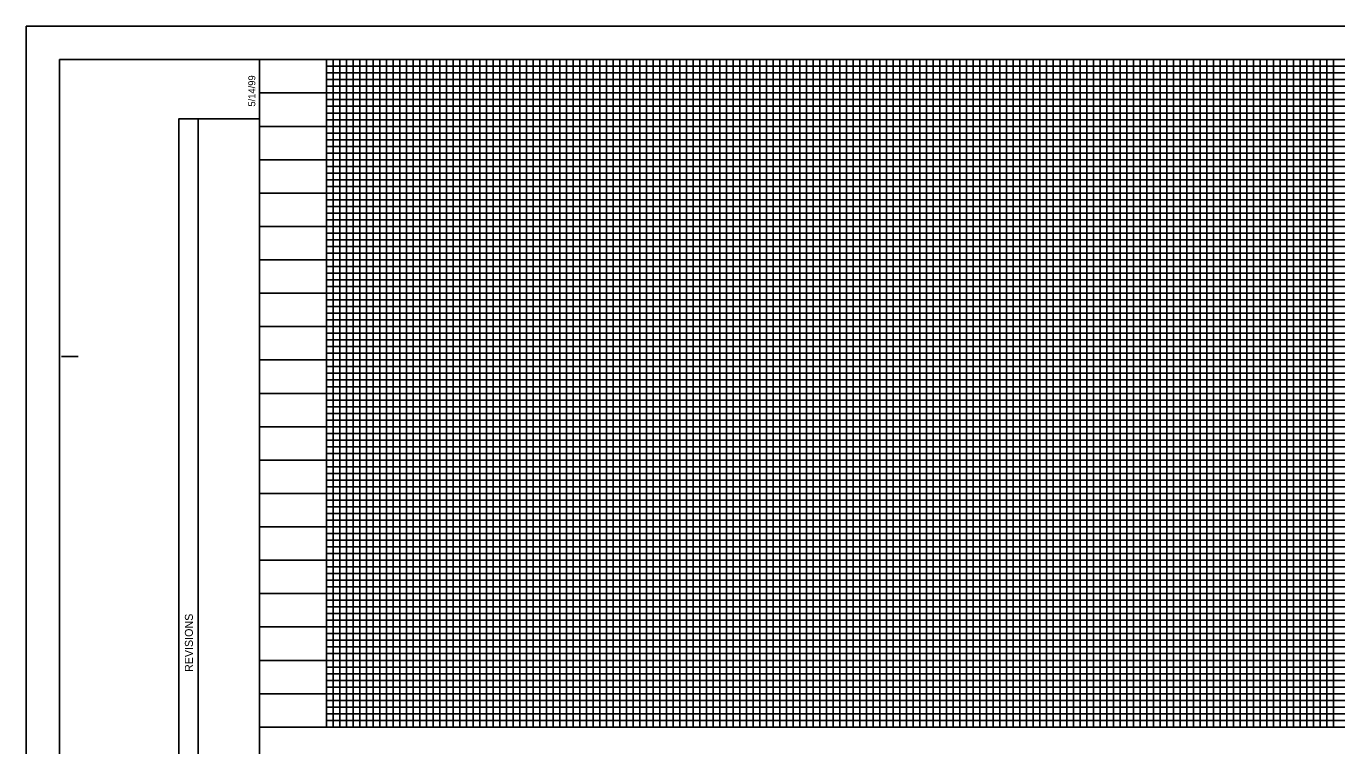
# Model space of a CAD drawing. Extents: x 1852853 to 1854818, y 258638 to 259738.
# Drawn here: x 1852853 to 1853836, y 259199 to 259738 of the extents above; entities that cross this region are included whole.
import ezdxf

# ---------------------------------------------------------------- set-up
doc = ezdxf.new("R2010")
doc.units = 0
for name, color, linetype in [('Old_Level_41', 7, 'Continuous'), ('Old_Level_43', 7, 'Continuous'), ('Old_Level_46', 7, 'Continuous'), ('Old_Level_62', 7, 'Continuous'), ('Old_Level_63', 7, 'Continuous'), ('Scratch_Level_3', 7, 'Continuous'), ('Sheet Block Revision CELL', 7, 'Continuous'), ('Sheet Profile CELL', 7, 'Continuous'), ('Sheet Profile Grid Major CELL', 7, 'Continuous'), ('Sheet Profile Grid Middle CELL', 7, 'Continuous'), ('Sheet Profile Grid Minor CELL', 7, 'Continuous')]:
    doc.layers.add(name, color=color, linetype=linetype)

msp = doc.modelspace()

# ---------------------------------------------------------------- linework, layer by layer
at = {"layer": 'Old_Level_41'}
msp.add_line((1852879.58, 259490.99), (1852892.08, 259490.99), dxfattribs=at)
at = {"layer": 'Old_Level_43'}
msp.add_line((1853078.08, 259703.49), (1853078.08, 259703.49), dxfattribs=at)
at = {"layer": 'Old_Level_46'}
msp.add_line((1853028.08, 259713.49), (1853028.08, 259713.49), dxfattribs=at)
at = {"layer": 'Old_Level_62'}
msp.add_lwpolyline([(1852878.08, 258663.49), (1854528.08, 258663.49), (1854528.08, 259713.49), (1852878.08, 259713.49)], close=True, dxfattribs=at)
at = {"layer": 'Old_Level_63'}
msp.add_lwpolyline([(1852853.08, 258638.49), (1854553.08, 258638.49), (1854553.08, 259738.49), (1852853.08, 259738.49)], close=True, dxfattribs=at)
at = {"layer": 'Scratch_Level_3'}
msp.add_lwpolyline([(1853078.08, 259713.49), (1853078.08, 259213.49), (1854478.08, 259213.49), (1854478.08, 259481.84), (1854328.03, 259481.84), (1854328.03, 259713.49)], close=True, dxfattribs=at)
at = {"layer": 'Sheet Block Revision CELL'}
msp.add_line((1852982.09, 258878.59), (1852982.08, 259669.23), dxfattribs=at)
msp.add_lwpolyline([(1852967.54, 258878.57), (1852967.54, 259669.22), (1853028.08, 259669.24), (1853028.08, 258878.59)], close=True, dxfattribs=at)
at = {"layer": 'Sheet Profile CELL'}
msp.add_line((1853028.08, 259213.49), (1854528.08, 259213.49), dxfattribs=at)
msp.add_lwpolyline([(1854528.08, 259713.49), (1853028.08, 259713.49), (1853028.08, 258663.49), (1854528.08, 258663.49)], close=True, dxfattribs=at)
at = {"layer": 'Sheet Profile Grid Major CELL'}
for points in [[(1854328.08, 259663.49), (1853028.08, 259663.49), (1853028.08, 259713.49), (1854328.08, 259713.49)], [(1853078.08, 259713.49), (1853078.08, 259213.49), (1853128.08, 259213.49), (1853128.08, 259713.49)], [(1853178.08, 259713.49), (1853178.08, 259213.49), (1853228.08, 259213.49), (1853228.08, 259713.49)], [(1853278.08, 259713.49), (1853278.08, 259213.49), (1853328.08, 259213.49), (1853328.08, 259713.49)], [(1853378.08, 259713.49), (1853378.08, 259213.49), (1853428.08, 259213.49), (1853428.08, 259713.49)], [(1853478.08, 259713.49), (1853478.08, 259213.49), (1853528.08, 259213.49), (1853528.08, 259713.49)], [(1853578.08, 259713.49), (1853578.08, 259213.49), (1853628.08, 259213.49), (1853628.08, 259713.49)], [(1853678.08, 259713.49), (1853678.08, 259213.49), (1853728.08, 259213.49), (1853728.08, 259713.49)], [(1853778.08, 259713.49), (1853778.08, 259213.49), (1853828.08, 259213.49), (1853828.08, 259713.49)], [(1854328.08, 259563.49), (1853028.08, 259563.49), (1853028.08, 259613.49), (1854328.08, 259613.49)], [(1854528.08, 259463.49), (1853028.08, 259463.49), (1853028.08, 259513.49), (1854328.03, 259513.49)], [(1854528.08, 259363.49), (1853028.08, 259363.49), (1853028.08, 259413.49), (1854528.08, 259413.49)], [(1854528.08, 259263.49), (1853028.08, 259263.49), (1853028.08, 259313.49), (1854528.08, 259313.49)]]:
    msp.add_lwpolyline(points, dxfattribs=at)
at = {"layer": 'Sheet Profile Grid Middle CELL'}
for points in [[(1853028.08, 259713.49), (1853028.08, 259688.49), (1854328.08, 259688.49)], [(1853103.08, 259213.49), (1853103.08, 259713.49)], [(1853153.08, 259713.49), (1853153.08, 259213.49), (1853203.08, 259213.49), (1853203.08, 259713.49)], [(1853253.08, 259713.49), (1853253.08, 259213.49), (1853303.08, 259213.49), (1853303.08, 259713.49)], [(1853353.08, 259713.49), (1853353.08, 259213.49), (1853403.08, 259213.49), (1853403.08, 259713.49)], [(1853453.08, 259713.49), (1853453.08, 259213.49), (1853503.08, 259213.49), (1853503.08, 259713.49)], [(1853553.08, 259713.49), (1853553.08, 259213.49), (1853603.08, 259213.49), (1853603.08, 259713.49)], [(1853653.08, 259713.49), (1853653.08, 259213.49), (1853703.08, 259213.49), (1853703.08, 259713.49)], [(1853753.08, 259713.49), (1853753.08, 259213.49), (1853803.08, 259213.49), (1853803.08, 259713.49)], [(1854328.08, 259638.49), (1853028.08, 259638.49), (1853028.08, 259588.49), (1854328.08, 259588.49)], [(1854328.08, 259538.49), (1853028.08, 259538.49), (1853028.08, 259488.49), (1854328.03, 259488.49)], [(1854528.08, 259438.49), (1853028.08, 259438.49), (1853028.08, 259388.49), (1854528.08, 259388.49)], [(1854528.08, 259338.49), (1853028.08, 259338.49), (1853028.08, 259288.49), (1854528.08, 259288.49)], [(1854528.08, 259238.49), (1853028.08, 259238.49)]]:
    msp.add_lwpolyline(points, dxfattribs=at)
at = {"layer": 'Sheet Profile Grid Minor CELL'}
for points in [[(1853078.08, 259708.49), (1854328.08, 259708.49)], [(1853083.08, 259713.49), (1853083.08, 259213.49), (1853088.08, 259213.49), (1853088.08, 259713.49)], [(1853093.08, 259713.49), (1853093.08, 259213.49), (1853098.08, 259213.49), (1853098.08, 259713.49)], [(1853108.08, 259713.49), (1853108.08, 259213.49), (1853113.08, 259213.49), (1853113.08, 259713.49)], [(1853118.08, 259713.49), (1853118.08, 259213.49), (1853123.08, 259213.49), (1853123.08, 259713.49)], [(1853133.08, 259713.49), (1853133.08, 259213.49), (1853138.08, 259213.49), (1853138.08, 259713.49)], [(1853143.08, 259713.49), (1853143.08, 259213.49), (1853148.08, 259213.49), (1853148.08, 259713.49)], [(1853158.08, 259713.49), (1853158.08, 259213.49), (1853163.08, 259213.49), (1853163.08, 259713.49)], [(1853168.08, 259713.49), (1853168.08, 259213.49), (1853173.08, 259213.49), (1853173.08, 259713.49)], [(1853183.08, 259713.49), (1853183.08, 259213.49), (1853188.08, 259213.49), (1853188.08, 259713.49)], [(1853193.08, 259713.49), (1853193.08, 259213.49), (1853198.08, 259213.49), (1853198.08, 259713.49)], [(1853208.08, 259713.49), (1853208.08, 259213.49), (1853213.08, 259213.49), (1853213.08, 259713.49)], [(1853218.08, 259713.49), (1853218.08, 259213.49), (1853223.08, 259213.49), (1853223.08, 259713.49)], [(1853233.08, 259713.49), (1853233.08, 259213.49), (1853238.08, 259213.49), (1853238.08, 259713.49)], [(1853243.08, 259213.49), (1853248.08, 259213.49), (1853248.08, 259713.49)], [(1853243.08, 259713.49), (1853243.08, 259213.49)], [(1853258.08, 259713.49), (1853258.08, 259213.49), (1853263.08, 259213.49), (1853263.08, 259713.49)], [(1853268.08, 259713.49), (1853268.08, 259213.49), (1853273.08, 259213.49), (1853273.08, 259713.49)], [(1853283.08, 259713.49), (1853283.08, 259213.49), (1853288.08, 259213.49), (1853288.08, 259713.49)], [(1853293.08, 259713.49), (1853293.08, 259213.49), (1853298.08, 259213.49), (1853298.08, 259713.49)], [(1853308.08, 259713.49), (1853308.08, 259213.49), (1853313.08, 259213.49), (1853313.08, 259713.49)], [(1853318.08, 259713.49), (1853318.08, 259213.49), (1853323.08, 259213.49), (1853323.08, 259713.49)], [(1853333.08, 259713.49), (1853333.08, 259213.49), (1853338.08, 259213.49), (1853338.08, 259713.49)], [(1853343.08, 259713.49), (1853343.08, 259213.49), (1853348.08, 259213.49), (1853348.08, 259713.49)], [(1853358.08, 259713.49), (1853358.08, 259213.49), (1853363.08, 259213.49), (1853363.08, 259713.49)], [(1853368.08, 259713.49), (1853368.08, 259213.49), (1853373.08, 259213.49), (1853373.08, 259713.49)], [(1853383.08, 259713.49), (1853383.08, 259213.49), (1853388.08, 259213.49), (1853388.08, 259713.49)], [(1853393.08, 259713.49), (1853393.08, 259213.49), (1853398.08, 259213.49), (1853398.08, 259713.49)], [(1853408.08, 259713.49), (1853408.08, 259213.49), (1853423.08, 259213.49), (1853423.08, 259713.49)], [(1853413.08, 259713.49), (1853413.08, 259213.49), (1853418.08, 259213.49), (1853418.08, 259713.49)], [(1853413.08, 259713.49), (1853413.08, 259213.49), (1853418.08, 259213.49), (1853418.08, 259713.49)], [(1853433.08, 259713.49), (1853433.08, 259213.49), (1853438.08, 259213.49), (1853438.08, 259713.49)], [(1853443.08, 259713.49), (1853443.08, 259213.49), (1853448.08, 259213.49), (1853448.08, 259713.49)], [(1853458.08, 259713.49), (1853458.08, 259213.49), (1853463.08, 259213.49), (1853463.08, 259713.49)], [(1853468.08, 259713.49), (1853468.08, 259213.49), (1853473.08, 259213.49), (1853473.08, 259713.49)], [(1853483.08, 259713.49), (1853483.08, 259213.49), (1853488.08, 259213.49), (1853488.08, 259713.49)], [(1853493.08, 259713.49), (1853493.08, 259213.49), (1853498.08, 259213.49), (1853498.08, 259713.49)], [(1853508.08, 259713.49), (1853508.08, 259213.49), (1853513.08, 259213.49), (1853513.08, 259713.49)], [(1853518.08, 259713.49), (1853518.08, 259213.49), (1853523.08, 259213.49), (1853523.08, 259713.49)], [(1853533.08, 259713.49), (1853533.08, 259213.49), (1853538.08, 259213.49), (1853538.08, 259713.49)], [(1853543.08, 259713.49), (1853543.08, 259213.49), (1853548.08, 259213.49), (1853548.08, 259713.49)], [(1853558.08, 259713.49), (1853558.08, 259213.49)], [(1853563.08, 259713.49), (1853563.08, 259213.49), (1853568.08, 259213.49), (1853568.08, 259713.49)], [(1853573.08, 259713.49), (1853573.08, 259213.49), (1853583.08, 259213.49), (1853583.08, 259713.49)], [(1853588.08, 259713.49), (1853588.08, 259213.49), (1853593.08, 259213.49), (1853593.08, 259713.49)], [(1853598.08, 259713.49), (1853598.08, 259213.49)], [(1853608.08, 259213.49), (1853608.08, 259713.49)], [(1853613.08, 259713.49), (1853613.08, 259213.49), (1853618.08, 259213.49), (1853618.08, 259713.49)], [(1853623.08, 259713.49), (1853623.08, 259213.49), (1853633.08, 259213.49), (1853633.08, 259713.49)], [(1853638.08, 259713.49), (1853638.08, 259213.49), (1853638.08, 259213.49), (1853643.08, 259213.49), (1853643.08, 259713.49)], [(1853648.08, 259713.49), (1853648.08, 259213.49), (1853658.08, 259213.49), (1853658.08, 259713.49)], [(1853663.08, 259713.49), (1853663.08, 259213.49), (1853668.08, 259213.49), (1853668.08, 259713.49)], [(1853673.08, 259713.49), (1853673.08, 259213.49), (1853683.08, 259213.49), (1853683.08, 259713.49)], [(1853688.08, 259713.49), (1853688.08, 259213.49), (1853693.08, 259213.49), (1853693.08, 259713.49)], [(1853698.08, 259713.49), (1853698.08, 259213.49), (1853708.08, 259213.49), (1853708.08, 259713.49)], [(1853713.08, 259713.49), (1853713.08, 259213.49), (1853718.08, 259213.49), (1853718.08, 259713.49)], [(1853723.08, 259713.49), (1853723.08, 259213.49), (1853733.08, 259213.49), (1853733.08, 259713.49)], [(1853738.08, 259713.49), (1853738.08, 259213.49), (1853743.08, 259213.49), (1853743.08, 259713.49)], [(1853748.08, 259713.49), (1853748.08, 259213.49), (1853758.08, 259213.49), (1853758.08, 259713.49)], [(1853763.08, 259713.49), (1853763.08, 259213.49), (1853768.08, 259213.49), (1853768.08, 259713.49)], [(1853773.08, 259713.49), (1853773.08, 259213.49), (1853783.08, 259213.49), (1853783.08, 259713.49)], [(1853788.08, 259713.49), (1853788.08, 259213.49)], [(1853788.08, 259213.49), (1853793.08, 259213.49), (1853793.08, 259713.49)], [(1853798.08, 259713.49), (1853798.08, 259213.49), (1853808.08, 259213.49), (1853808.08, 259713.49)], [(1853813.08, 259713.49), (1853813.08, 259213.49), (1853818.08, 259213.49), (1853818.08, 259713.49)], [(1853823.08, 259713.49), (1853823.08, 259213.49), (1853833.08, 259213.49), (1853833.08, 259713.49)], [(1854328.08, 259703.49), (1853078.08, 259703.49), (1853078.08, 259698.49), (1854328.08, 259698.49)], [(1854328.08, 259693.49), (1853078.08, 259693.49), (1853078.08, 259683.49), (1854328.08, 259683.49)], [(1854328.08, 259678.49), (1853078.08, 259678.49), (1853078.08, 259673.49), (1854328.08, 259673.49)], [(1854328.08, 259668.49), (1853078.08, 259668.49), (1853078.08, 259658.49), (1854328.08, 259658.49)], [(1854328.08, 259653.49), (1853078.08, 259653.49), (1853078.08, 259648.49), (1854328.08, 259648.49)], [(1854328.08, 259643.49), (1853078.08, 259643.49), (1853078.08, 259633.49), (1854328.08, 259633.49)], [(1854328.08, 259628.49), (1853078.08, 259628.49), (1853078.08, 259623.49), (1854328.08, 259623.49)], [(1854328.08, 259618.49), (1853078.08, 259618.49), (1853078.08, 259608.49), (1854328.08, 259608.49)], [(1854328.08, 259603.49), (1853078.08, 259603.49), (1853078.08, 259598.49), (1854328.08, 259598.49)], [(1854328.08, 259593.49), (1853078.08, 259593.49), (1853078.08, 259583.49), (1854328.08, 259583.49)], [(1854328.08, 259578.49), (1853078.08, 259578.49), (1853078.08, 259573.49), (1854328.08, 259573.49)], [(1854328.08, 259568.49), (1853078.08, 259568.49), (1853078.08, 259558.49), (1854328.08, 259558.49)], [(1854328.08, 259553.49), (1853078.08, 259553.49), (1853078.08, 259548.49), (1854328.08, 259548.49)], [(1854328.08, 259543.49), (1853078.08, 259543.49), (1853078.08, 259533.49), (1854328.08, 259533.49)], [(1854328.08, 259528.49), (1853078.08, 259528.49), (1853078.08, 259523.49), (1854328.08, 259523.49)], [(1854328.08, 259518.49), (1853078.08, 259518.49), (1853078.08, 259508.49), (1854328.03, 259508.49)], [(1854328.03, 259503.49), (1853078.08, 259503.49), (1853078.08, 259498.49), (1854328.03, 259498.49)], [(1854328.03, 259493.49), (1853078.08, 259493.49), (1853078.08, 259483.49), (1854328.03, 259483.49)], [(1854478.08, 259478.49), (1853078.08, 259478.49), (1853078.08, 259473.49), (1854478.08, 259473.49)], [(1854478.08, 259468.49), (1853078.08, 259468.49), (1853078.08, 259458.49), (1854478.08, 259458.49)], [(1854478.08, 259453.49), (1853078.08, 259453.49), (1853078.08, 259448.49), (1854478.08, 259448.49)], [(1854478.08, 259443.49), (1853078.08, 259443.49), (1853078.08, 259433.49), (1854478.08, 259433.49)], [(1854478.08, 259428.49), (1853078.08, 259428.49), (1853078.08, 259423.49), (1854478.08, 259423.49)], [(1854478.08, 259418.49), (1853078.08, 259418.49)], [(1853078.08, 259408.49), (1854478.08, 259408.49)], [(1854478.08, 259403.49), (1853078.08, 259403.49), (1853078.08, 259398.49), (1854478.08, 259398.49)], [(1854478.08, 259393.49), (1853078.08, 259393.49)], [(1853078.08, 259383.49), (1854478.08, 259383.49)], [(1854478.08, 259378.49), (1853078.08, 259378.49), (1853078.08, 259373.49), (1854478.08, 259373.49)], [(1854478.08, 259368.49), (1853078.08, 259368.49), (1853078.08, 259358.49), (1854478.08, 259358.49)], [(1854478.08, 259353.49), (1853078.08, 259353.49), (1853078.08, 259348.49), (1854478.08, 259348.49)], [(1854478.08, 259343.49), (1853078.08, 259343.49), (1853078.08, 259333.49), (1854478.08, 259333.49)], [(1854478.08, 259328.49), (1853078.08, 259328.49), (1853078.08, 259323.49), (1854478.08, 259323.49)], [(1854478.08, 259318.49), (1853078.08, 259318.49), (1853078.08, 259308.49), (1854478.08, 259308.49)], [(1854478.08, 259303.49), (1853078.08, 259303.49), (1853078.08, 259298.49), (1854478.08, 259298.49)], [(1854478.08, 259293.49), (1853078.08, 259293.49), (1853078.08, 259283.49), (1854478.08, 259283.49)], [(1854478.08, 259278.49), (1853078.08, 259278.49), (1853078.08, 259273.49), (1854478.08, 259273.49)], [(1854478.08, 259268.49), (1853078.08, 259268.49), (1853078.08, 259258.49), (1854478.08, 259258.49)], [(1854478.08, 259253.49), (1853078.08, 259253.49), (1853078.08, 259248.49), (1854478.08, 259248.49)], [(1854478.08, 259243.49), (1853078.08, 259243.49), (1853078.08, 259233.49), (1854478.08, 259233.49)], [(1854478.08, 259228.49), (1853078.08, 259228.49), (1853078.08, 259223.49), (1854478.08, 259223.49)], [(1854478.08, 259218.49), (1853078.08, 259218.49), (1853078.08, 259213.49), (1854478.08, 259213.49)]]:
    msp.add_lwpolyline(points, dxfattribs=at)

# ---------------------------------------------------------------- texts
at = {"layer": 'Sheet Block Revision CELL'}
msp.add_text('REVISIONS', height=6, rotation=90, dxfattribs=at).set_placement((1852978.04, 259254.74))
at = {"layer": 'Sheet Profile CELL'}
msp.add_text('5/14/99', height=5.25, rotation=90, dxfattribs=at).set_placement((1853024.83, 259678.29))

doc.saveas('drawing.dxf')
